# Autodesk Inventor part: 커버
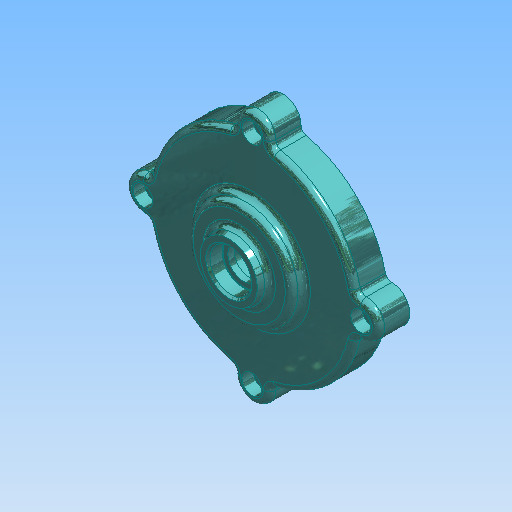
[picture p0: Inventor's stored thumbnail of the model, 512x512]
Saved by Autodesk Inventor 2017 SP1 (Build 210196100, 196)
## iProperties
Created: 2021-07
Part Number: 커버
Document SubType Name: 모델링
Designer: mdu
Material: 알루미늄 6061
Density: 2.71 g/cm^3
Mass: 196.659 g
Surface Area: 278.607 cm^2
Volume: 72.5678 cm^3
Appearance: 커버
변환 표준: STEP AP214IS
파일 이름: C:\Users\SeoGD\Desktop\?쒗뿕\而ㅻ쾭-1.stp
전처리기: Build: 253, Release: 2010 SP1 - Date: Wed 07/29/2009
전송 단위: 밀리미터
불확실성: 0.01
Author: mdu
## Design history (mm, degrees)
sketch "스케치1"
  geometry: L1 (0, 0)-(0, 26); L2 (50, 0)-(50, 15); L3 (50, 15)-(25, 15); L4 (25, 15)-(25, 21); L5 (25, 21)-(15, 21); L6 (15, 21)-(13.66, 26); L7 (13.66, 26)-(10, 26); L8 (50, 0)-(45, 0); L9 (45, 0)-(45, 10); L10 (45, 10)-(14.5, 10); L11 (14.5, 10)-(13.266, 3); L12 (13.266, 3)-(11, 3); L13 (11, 3)-(11, 16); L14 (11, 16)-(7.5, 16); L15 (7.5, 16)-(7.5, 19); L16 (7.5, 19)-(10, 19); L17 (10, 19)-(10, 26)
  constraints: 34 end point, 10 parallel, 2 perpendicular, 2 point on line, 1 vertical
  dimensions: "d11" = 100 diameter of L2 L1; "d12" = 22 diameter of L13 L1; "d13" = 90 diameter of L9 L1; "d14" = 15 distance between parallel lines of L3 L8; "d15" = 10 distance between parallel lines of L8 L10; "d16" = 29 diameter of L10.end L1; "d17" = 100 deg angle of L11 L10; "d18" = 7 distance between parallel lines of L12 L10; "d19" = 13 distance between parallel lines of L14 L12; "d20" = 3 distance between parallel lines of L16 L14; "d21" = 15 diameter of L15 L1; "d22" = 20 diameter of L17 L1; "d23" = 30 diameter of L5.end L1; "d24" = 6 distance between parallel lines of L5 L3; "d25" = 50 diameter of L4 L1; "d26" = 105 deg angle of L5 L6; "d50" = 26 distance of L1.start L1.end
revolve "회전1" sketch "스케치1" stored, may be unused: angle "d27" = 90 deg
sketch "스케치2" dims "d29" = 104
  geometry: A1 r 8.5 centre (0, 52) between (8.074, 49.344) and (-8.074, 49.344); A2 r 50 centre (0, 0) between (-8.074, 49.344) and (8.074, 49.344) reference; 2 further points
  constraints: 4 point on circle, 2 vertical alignment, 1 centre point, 1 coincident, 2 other
  dimensions: "d28" = 17 diameter of A1
extrude "돌출1" join sketch "스케치2" stored distance "d30" = 10; taper "d31" = 0 deg
fillet "모깎기3" dims "d32" = 3
fillet "모깎기4" dims "d45" = 3, "d46" = 0.2
chamfer "모따기1" distance "d47" = 1; stored, may be unused: second distance "d48" = 2, angle "d49" = 45 deg
hole "구멍2" diameter "d38" = 5.5; stored, may be unused: countersink angle "d42" = 90 deg, drill point angle "d44" = 118 deg; dims "d36" = 10, "d37" = 10, "d39" = 6, "d40" = 9.5, "d41" = 5.4, "d43" = 8
node "솔리드1"
node "솔리드 본체"
node "곡면 본체"
pattern_circular "원형 패턴1" dims angle "d34" = 360 deg
pattern_circular "원형 패턴2" dims angle "d52" = 360 deg
node "솔리드2"
